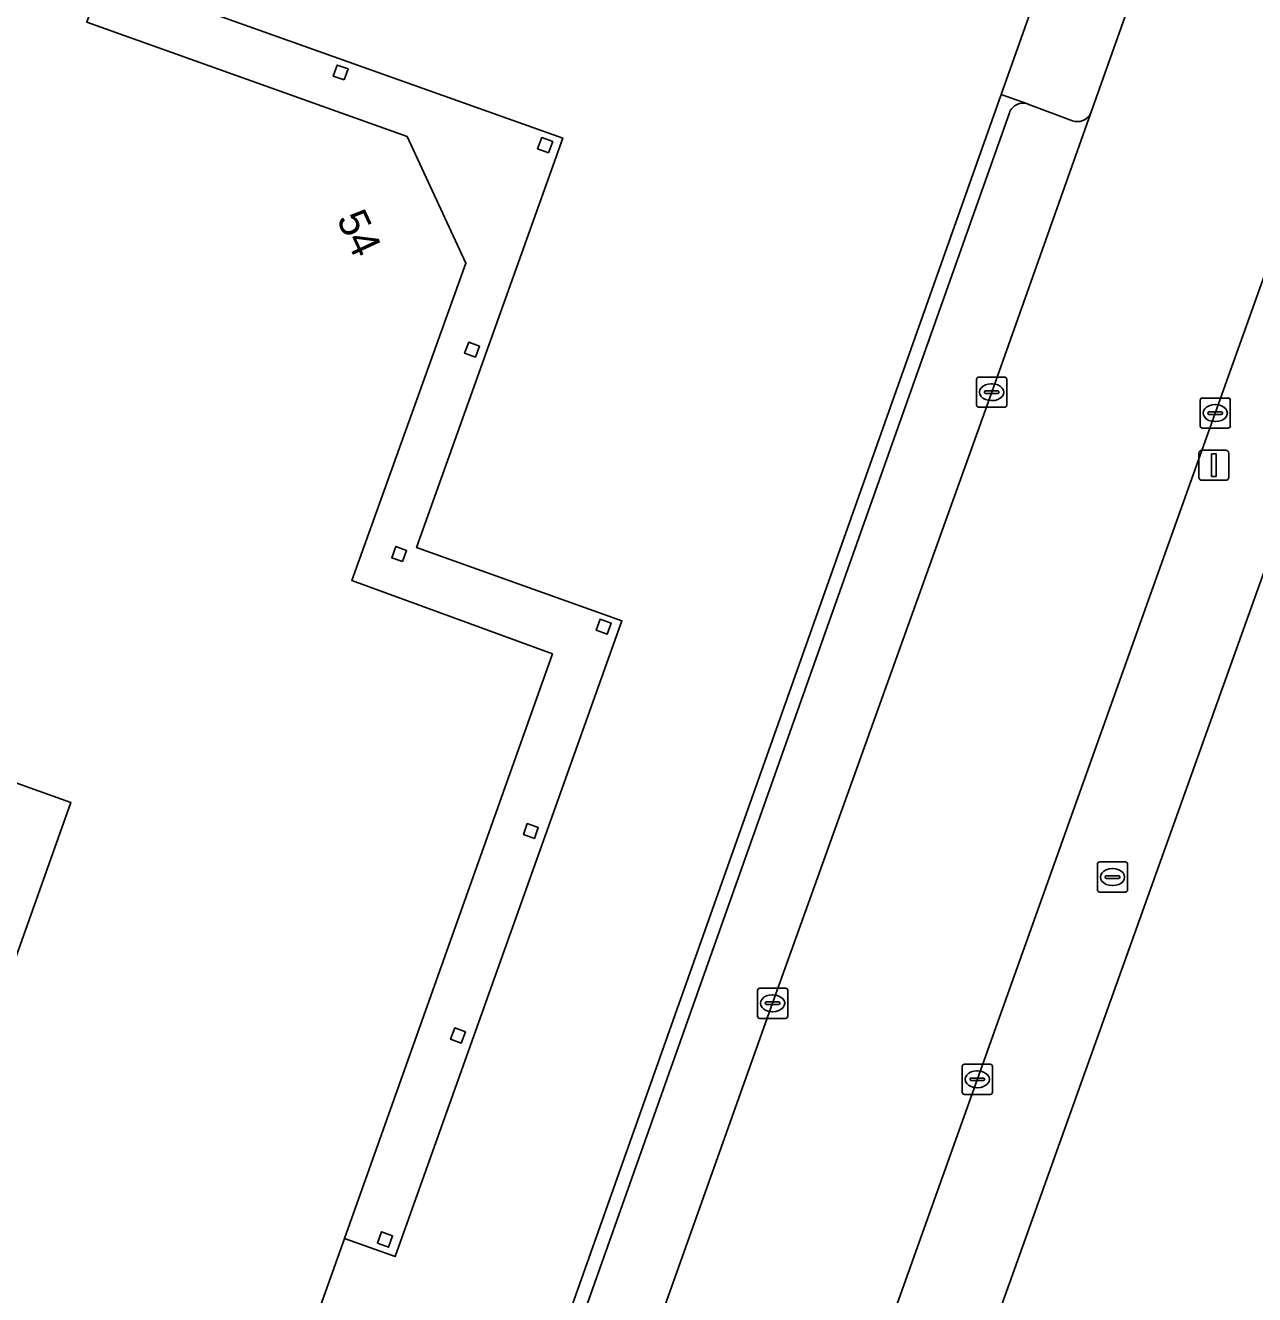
# Model space of a CAD drawing. Extents: x 155018 to 156648, y 383979 to 385733.
# Drawn here: x 155717.08 to 155757.84, y 385071.83 to 385113.92 of the extents above; entities that cross this region are included whole.
import ezdxf

# ---------------------------------------------------------------- set-up
doc = ezdxf.new("R2010")
doc.units = 0
for name, color, linetype in [('IMGEO_Brandkraan', 7, 'Continuous'), ('IMGEO_Erf', 7, 'Continuous'), ('IMGEO_Kolk', 7, 'Continuous'), ('IMGEO_Lichtmast', 7, 'Continuous'), ('IMGEO_Pand', 7, 'Continuous'), ('IMGEO_Pand_nummerreeks', 7, 'Continuous'), ('IMGEO_Pand_overbouw', 7, 'Continuous'), ('IMGEO_Parkeervlak_open', 7, 'Continuous'), ('IMGEO_Rijbaan_lokaal_gesloten', 7, 'Continuous'), ('IMGEO_Voetpad_open', 7, 'Continuous')]:
    doc.layers.add(name, color=color, linetype=linetype)

msp = doc.modelspace()

# ---------------------------------------------------------------- linework, layer by layer
at = {"layer": 'IMGEO_Brandkraan'}
for p, q in [((155752.632, 385085.25), (155752.632, 385086.102)), ((155752.707, 385086.176), (155753.559, 385086.176)), ((155753.12, 385085.956), (155753.145, 385085.956)), ((155753.633, 385086.102), (155753.633, 385085.25)), ((155752.891, 385085.67), (155752.891, 385085.682)), ((155753.329, 385085.633), (155752.931, 385085.633)), ((155752.934, 385085.719), (155753.332, 385085.719)), ((155753.375, 385085.682), (155753.375, 385085.67)), ((155753.559, 385085.176), (155752.707, 385085.176)), ((155753.143, 385085.396), (155753.118, 385085.396))]:
    msp.add_line(p, q, dxfattribs=at)
for points in [[(155752.632, 385085.25), (155752.632, 385086.102)], [(155752.707, 385086.176), (155753.559, 385086.176)], [(155753.633, 385086.102), (155753.633, 385085.25)], [(155753.559, 385085.176), (155752.707, 385085.176)]]:
    msp.add_lwpolyline(points, dxfattribs=at)
for centre, radius, start, end in [((155752.709, 385086.1), 0.0765, 91.552, 178.448), ((155752.709, 385086.1), 0.0765, 91.552, 178.448), ((155753.557, 385086.1), 0.0765, 1.552, 88.448), ((155753.557, 385086.1), 0.0765, 1.552, 88.448), ((155752.931, 385085.679), 0.0403, 85.8775, 175.7526), ((155752.928, 385085.669), 0.0366, 178.938, 274.7102), ((155753.332, 385085.676), 0.043, 264.8664, 352.4533), ((155753.336, 385085.681), 0.0386, 1.7309, 96.639), ((155752.709, 385085.252), 0.0765, 181.552, 268.448), ((155752.709, 385085.252), 0.0765, 181.552, 268.448), ((155753.557, 385085.252), 0.0765, 271.552, 358.448), ((155753.557, 385085.252), 0.0765, 271.552, 358.448)]:
    msp.add_arc(centre, radius, start, end, dxfattribs=at)
for centre, major_axis, ratio, start_param, end_param in [((155753.119, 385085.676), (-0.387, 0.002), 0.722429, 4.712389, 7.853982), ((155753.144, 385085.676), (-0.39, 0.002), 0.717154, 1.570796, 4.712389)]:
    msp.add_ellipse(centre, major_axis=major_axis, ratio=ratio, start_param=start_param, end_param=end_param, dxfattribs=at)
at = {"layer": 'IMGEO_Erf'}
for points in [[(155694.342, 384956.978), (155694.915, 384958.585), (155709.077, 384998.076), (155709.767, 385000), (155717.522, 385021.627), (155721.797, 385033.581), (155723.78, 385039.191), (155749.439, 385111.623), (155754.279, 385125.284), (155751.396, 385130.416), (155717.596, 385142.395), (155670.014, 385159.249), (155661.245, 385162.355), (155620.236, 385176.93), (155602.298, 385183.305), (155601.269, 385183.671), (155551.448, 385201.401), (155546.604, 385198.733), (155542.42, 385187.249), (155529.708, 385151.464), (155526.702, 385143.011), (155526.061, 385141.208), (155524.297, 385136.458), (155523.434, 385136.779)], [(155841.725, 385076.189), (155812.458, 385090.276), (155811.925, 385090.532), (155810.841, 385091.052), (155764.43, 385113.324), (155764.255, 385112.835), (155733.568, 385027.069), (155733.054, 385025.589), (155730.642, 385018.653)]]:
    msp.add_lwpolyline(points, dxfattribs=at)
for points in [[(155670.263, 385124.691), (155674.13, 385128.38), (155672.13, 385129.15), (155674.66, 385131.64), (155676.67, 385130.92), (155681.04, 385135.1), (155695.29, 385130.022), (155721.45, 385120.7), (155719.12, 385114.03), (155729.74, 385110.24), (155731.69, 385106.03), (155727.91, 385095.51), (155734.56, 385093.08), (155727.662, 385073.693), (155721.63, 385056.74), (155716.5, 385058.59), (155715.32, 385055.2), (155712.89, 385057.75), (155713.52, 385059.62), (155709.03, 385061.25), (155718.594, 385088.148), (155701.503, 385094.257), (155707.612, 385111.348)], [(155727.65, 385112.111), (155727.294, 385112.24), (155727.427, 385112.606), (155727.783, 385112.477)], [(155734.431, 385109.695), (155734.071, 385109.831), (155734.21, 385110.199), (155734.57, 385110.064)], [(155732.01, 385102.912), (155731.65, 385103.046), (155731.786, 385103.412), (155732.146, 385103.279)], [(155729.587, 385096.136), (155729.23, 385096.266), (155729.367, 385096.641), (155729.723, 385096.511)], [(155736.01, 385093.859), (155736.142, 385094.227), (155736.504, 385094.097), (155736.372, 385093.729)], [(155733.602, 385087.084), (155733.725, 385087.448), (155734.09, 385087.325), (155733.966, 385086.96)], [(155731.184, 385080.3), (155731.322, 385080.676), (155731.674, 385080.547), (155731.537, 385080.171)], [(155728.756, 385073.538), (155728.895, 385073.912), (155729.263, 385073.776), (155729.125, 385073.402)]]:
    msp.add_lwpolyline(points, close=True, dxfattribs=at)
at = {"layer": 'IMGEO_Kolk'}
for p, q in [((155748.624, 385101.33), (155748.624, 385102.182)), ((155748.699, 385102.256), (155749.551, 385102.256)), ((155749.112, 385102.036), (155749.137, 385102.036)), ((155749.625, 385102.182), (155749.625, 385101.33)), ((155748.883, 385101.75), (155748.883, 385101.762)), ((155749.321, 385101.713), (155748.923, 385101.713)), ((155748.926, 385101.799), (155749.324, 385101.799)), ((155749.135, 385101.476), (155749.11, 385101.476)), ((155749.367, 385101.762), (155749.367, 385101.75)), ((155756.038, 385100.637), (155756.038, 385101.489)), ((155756.113, 385101.563), (155756.965, 385101.563)), ((155757.039, 385101.489), (155757.039, 385100.637)), ((155749.551, 385101.256), (155748.699, 385101.256)), ((155756.297, 385101.057), (155756.297, 385101.069)), ((155756.735, 385101.02), (155756.337, 385101.02)), ((155756.34, 385101.106), (155756.738, 385101.106)), ((155756.526, 385101.343), (155756.551, 385101.343)), ((155756.781, 385101.069), (155756.781, 385101.057)), ((155756.549, 385100.783), (155756.524, 385100.783)), ((155756.965, 385100.563), (155756.113, 385100.563)), ((155741.361, 385081.064), (155741.361, 385081.916)), ((155741.436, 385081.99), (155742.288, 385081.99)), ((155741.849, 385081.77), (155741.874, 385081.77)), ((155742.362, 385081.916), (155742.362, 385081.064)), ((155741.62, 385081.484), (155741.62, 385081.496)), ((155742.058, 385081.447), (155741.66, 385081.447)), ((155741.663, 385081.533), (155742.061, 385081.533)), ((155742.104, 385081.496), (155742.104, 385081.484)), ((155742.288, 385080.99), (155741.436, 385080.99)), ((155741.872, 385081.21), (155741.847, 385081.21)), ((155748.149, 385078.543), (155748.149, 385079.395)), ((155748.224, 385079.469), (155749.076, 385079.469)), ((155748.637, 385079.249), (155748.662, 385079.249)), ((155749.15, 385079.395), (155749.15, 385078.543)), ((155748.408, 385078.963), (155748.408, 385078.975)), ((155748.846, 385078.926), (155748.448, 385078.926)), ((155748.451, 385079.012), (155748.849, 385079.012)), ((155748.892, 385078.975), (155748.892, 385078.963)), ((155749.076, 385078.469), (155748.224, 385078.469)), ((155748.66, 385078.689), (155748.635, 385078.689))]:
    msp.add_line(p, q, dxfattribs=at)
for points in [[(155748.624, 385101.33), (155748.624, 385102.182)], [(155748.699, 385102.256), (155749.551, 385102.256)], [(155749.625, 385102.182), (155749.625, 385101.33)], [(155756.038, 385100.637), (155756.038, 385101.489)], [(155756.113, 385101.563), (155756.965, 385101.563)], [(155757.039, 385101.489), (155757.039, 385100.637)], [(155749.551, 385101.256), (155748.699, 385101.256)], [(155756.965, 385100.563), (155756.113, 385100.563)], [(155741.361, 385081.064), (155741.361, 385081.916)], [(155741.436, 385081.99), (155742.288, 385081.99)], [(155742.362, 385081.916), (155742.362, 385081.064)], [(155742.288, 385080.99), (155741.436, 385080.99)], [(155748.149, 385078.543), (155748.149, 385079.395)], [(155748.224, 385079.469), (155749.076, 385079.469)], [(155749.15, 385079.395), (155749.15, 385078.543)], [(155749.076, 385078.469), (155748.224, 385078.469)]]:
    msp.add_lwpolyline(points, dxfattribs=at)
for centre, radius, start, end in [((155748.701, 385102.18), 0.0765, 91.552, 178.448), ((155748.701, 385102.18), 0.0765, 91.552, 178.448), ((155749.549, 385102.18), 0.0765, 1.552, 88.448), ((155749.549, 385102.18), 0.0765, 1.552, 88.448), ((155748.923, 385101.759), 0.0403, 85.8775, 175.7526), ((155748.92, 385101.749), 0.0366, 178.938, 274.7102), ((155749.324, 385101.756), 0.043, 264.8664, 352.4533), ((155749.328, 385101.761), 0.0386, 1.7309, 96.639), ((155756.115, 385101.487), 0.0765, 91.552, 178.448), ((155756.115, 385101.487), 0.0765, 91.552, 178.448), ((155756.963, 385101.487), 0.0765, 1.552, 88.448), ((155756.963, 385101.487), 0.0765, 1.552, 88.448), ((155748.701, 385101.332), 0.0765, 181.552, 268.448), ((155748.701, 385101.332), 0.0765, 181.552, 268.448), ((155749.549, 385101.332), 0.0765, 271.552, 358.448), ((155749.549, 385101.332), 0.0765, 271.552, 358.448), ((155756.337, 385101.066), 0.0403, 85.8775, 175.7526), ((155756.334, 385101.056), 0.0366, 178.938, 274.7102), ((155756.738, 385101.063), 0.043, 264.8664, 352.4533), ((155756.742, 385101.068), 0.0386, 1.7309, 96.639), ((155756.115, 385100.639), 0.0765, 181.552, 268.448), ((155756.115, 385100.639), 0.0765, 181.552, 268.448), ((155756.963, 385100.639), 0.0765, 271.552, 358.448), ((155756.963, 385100.639), 0.0765, 271.552, 358.448), ((155741.438, 385081.914), 0.0765, 91.552, 178.448), ((155741.438, 385081.914), 0.0765, 91.552, 178.448), ((155742.286, 385081.914), 0.0765, 1.552, 88.448), ((155742.286, 385081.914), 0.0765, 1.552, 88.448), ((155741.66, 385081.493), 0.0403, 85.8775, 175.7526), ((155741.657, 385081.483), 0.0366, 178.938, 274.7102), ((155742.061, 385081.49), 0.043, 264.8664, 352.4533), ((155742.065, 385081.495), 0.0386, 1.7309, 96.639), ((155741.438, 385081.066), 0.0765, 181.552, 268.448), ((155741.438, 385081.066), 0.0765, 181.552, 268.448), ((155742.286, 385081.066), 0.0765, 271.552, 358.448), ((155742.286, 385081.066), 0.0765, 271.552, 358.448), ((155748.226, 385079.393), 0.0765, 91.552, 178.448), ((155748.226, 385079.393), 0.0765, 91.552, 178.448), ((155749.074, 385079.393), 0.0765, 1.552, 88.448), ((155749.074, 385079.393), 0.0765, 1.552, 88.448), ((155748.448, 385078.972), 0.0403, 85.8775, 175.7526), ((155748.445, 385078.962), 0.0366, 178.938, 274.7102), ((155748.849, 385078.969), 0.043, 264.8664, 352.4533), ((155748.853, 385078.974), 0.0386, 1.7309, 96.639), ((155748.226, 385078.545), 0.0765, 181.552, 268.448), ((155748.226, 385078.545), 0.0765, 181.552, 268.448), ((155749.074, 385078.545), 0.0765, 271.552, 358.448), ((155749.074, 385078.545), 0.0765, 271.552, 358.448)]:
    msp.add_arc(centre, radius, start, end, dxfattribs=at)
for centre, major_axis, ratio, start_param, end_param in [((155749.111, 385101.756), (-0.387, 0.002), 0.722429, 4.712389, 7.853982), ((155749.136, 385101.756), (-0.39, 0.002), 0.717154, 1.570796, 4.712389), ((155756.525, 385101.063), (-0.387, 0.002), 0.722429, 4.712389, 7.853982), ((155756.55, 385101.063), (-0.39, 0.002), 0.717154, 1.570796, 4.712389), ((155741.848, 385081.49), (-0.387, 0.002), 0.722429, 4.712389, 7.853982), ((155741.873, 385081.49), (-0.39, 0.002), 0.717154, 1.570796, 4.712389), ((155748.636, 385078.969), (-0.387, 0.002), 0.722429, 4.712389, 7.853982), ((155748.661, 385078.969), (-0.39, 0.002), 0.717154, 1.570796, 4.712389)]:
    msp.add_ellipse(centre, major_axis=major_axis, ratio=ratio, start_param=start_param, end_param=end_param, dxfattribs=at)
at = {"layer": 'IMGEO_Lichtmast'}
for p, q in [((155756.099, 385099.834), (155756.889, 385099.834)), ((155756.889, 385099.834), (155756.099, 385099.834)), ((155755.999, 385098.934), (155755.999, 385099.734)), ((155755.999, 385099.734), (155755.999, 385098.934)), ((155756.989, 385099.734), (155756.989, 385098.934)), ((155756.989, 385098.934), (155756.989, 385099.734)), ((155756.889, 385098.834), (155756.099, 385098.834)), ((155756.099, 385098.834), (155756.889, 385098.834))]:
    msp.add_line(p, q, dxfattribs=at)
msp.add_lwpolyline([(155756.419, 385099.709), (155756.569, 385099.709), (155756.569, 385098.959), (155756.419, 385098.959), (155756.419, 385099.709)], dxfattribs=at)
for centre, start, end in [((155756.099, 385099.734), 90, 180), ((155756.099, 385099.734), 90, 180), ((155756.889, 385099.734), 0, 90), ((155756.889, 385099.734), 360, 90), ((155756.099, 385098.934), 180, 270), ((155756.099, 385098.934), 180, 270), ((155756.889, 385098.934), 270, 0), ((155756.889, 385098.934), 270, 0)]:
    msp.add_arc(centre, 0.1, start, end, dxfattribs=at)
at = {"layer": 'IMGEO_Pand'}
for points in [[(155695.29, 385130.022), (155681.04, 385135.1), (155676.67, 385130.92), (155674.66, 385131.64), (155672.13, 385129.15), (155674.13, 385128.38), (155670.263, 385124.691), (155707.612, 385111.348), (155701.503, 385094.257), (155718.594, 385088.148), (155709.03, 385061.25), (155713.52, 385059.62), (155712.89, 385057.75), (155715.32, 385055.2), (155716.5, 385058.59), (155721.63, 385056.74), (155727.662, 385073.693), (155734.56, 385093.08), (155727.91, 385095.51), (155731.69, 385106.03), (155729.74, 385110.24), (155719.12, 385114.03), (155721.45, 385120.7)], [(155727.65, 385112.111), (155727.783, 385112.477), (155727.427, 385112.606), (155727.294, 385112.24)], [(155734.431, 385109.695), (155734.57, 385110.064), (155734.21, 385110.199), (155734.071, 385109.831)], [(155732.01, 385102.912), (155732.146, 385103.279), (155731.786, 385103.412), (155731.65, 385103.046)], [(155729.587, 385096.136), (155729.723, 385096.511), (155729.367, 385096.641), (155729.23, 385096.266)], [(155736.372, 385093.729), (155736.504, 385094.097), (155736.142, 385094.227), (155736.01, 385093.859)], [(155733.966, 385086.96), (155734.09, 385087.325), (155733.725, 385087.448), (155733.602, 385087.084)], [(155731.537, 385080.171), (155731.674, 385080.547), (155731.322, 385080.676), (155731.184, 385080.3)], [(155729.125, 385073.402), (155729.263, 385073.776), (155728.895, 385073.912), (155728.756, 385073.538)]]:
    msp.add_lwpolyline(points, close=True, dxfattribs=at)
at = {"layer": 'IMGEO_Pand_overbouw'}
msp.add_lwpolyline([(155695.89, 385131.702), (155695.29, 385130.022), (155721.45, 385120.7), (155719.12, 385114.03), (155729.74, 385110.24), (155731.69, 385106.03), (155727.91, 385095.51), (155734.56, 385093.08), (155727.662, 385073.693), (155729.342, 385073.093), (155736.863, 385094.173), (155730.056, 385096.601), (155734.902, 385110.184), (155721.359, 385115.016), (155723.764, 385121.757)], close=True, dxfattribs=at)
at = {"layer": 'IMGEO_Parkeervlak_open'}
for points in [[(155751.804, 385110.752), (155750.359, 385111.297)], [(155749.712, 385111.016), (155724.175, 385038.957), (155722.456, 385033.926), (155724.606, 385033.163), (155727.42, 385041.095), (155734.635, 385061.204)], [(155734.635, 385061.204), (155741.863, 385081.49), (155749.126, 385101.756), (155752.407, 385110.986)]]:
    msp.add_lwpolyline(points, dxfattribs=at)
for centre, radius, start, end in [((155750.163, 385110.864), 0.476, 65.614, 161.3377), ((155751.961, 385111.24), 0.513, 252.133, 330.2854)]:
    msp.add_arc(centre, radius, start, end, dxfattribs=at)
at = {"layer": 'IMGEO_Rijbaan_lokaal_gesloten'}
for points in [[(155764.837, 385117.429), (155755.507, 385119.738), (155752.407, 385110.986), (155749.126, 385101.756), (155741.863, 385081.49), (155734.635, 385061.204), (155727.42, 385041.095), (155724.606, 385033.163), (155719.998, 385020.177), (155712.839, 385000), (155711.66, 384996.694), (155697.277, 384956.434), (155683.176, 384916.819), (155680.471, 384909.27), (155672.406, 384886.601)], [(155679.062, 384884.306), (155679.409, 384885.386), (155683.078, 384895.663), (155693.322, 384923.959), (155698.719, 384939.029), (155712.551, 384977.822), (155712.738, 384978.347), (155715.089, 384984.941), (155720.459, 385000), (155723.632, 385008.98), (155724.976, 385012.761), (155727.017, 385018.428), (155728.003, 385021.255), (155731.055, 385029.838), (155733.848, 385037.615), (155741.439, 385058.768), (155756.537, 385101.063), (155759.644, 385109.754)]]:
    msp.add_lwpolyline(points, dxfattribs=at)
at = {"layer": 'IMGEO_Voetpad_open'}
for points in [[(155755.697, 385127.53), (155751.396, 385130.416), (155754.279, 385125.284), (155749.439, 385111.623), (155750.315, 385111.323), (155750.359, 385111.297), (155751.804, 385110.752)], [(155752.407, 385110.986), (155755.507, 385119.738)], [(155759.644, 385109.754), (155756.537, 385101.063), (155741.439, 385058.768), (155733.848, 385037.615), (155731.055, 385029.838), (155728.003, 385021.255), (155727.017, 385018.428), (155728.134, 385018.023), (155726.108, 385012.352), (155724.976, 385012.761), (155723.632, 385008.98), (155720.459, 385000), (155715.089, 384984.941), (155718.276, 384983.804), (155724.057, 385000), (155730.413, 385017.993), (155730.642, 385018.653), (155733.054, 385025.589), (155733.568, 385027.069), (155764.255, 385112.835)], [(155750.359, 385111.297), (155750.315, 385111.323), (155749.439, 385111.623), (155723.78, 385039.191), (155721.797, 385033.581)], [(155722.426, 385033.838), (155722.456, 385033.926), (155724.175, 385038.957), (155749.712, 385111.016)]]:
    msp.add_lwpolyline(points, dxfattribs=at)
for centre, radius, start, end in [((155750.163, 385110.864), 0.476, 65.614, 161.3377), ((155751.961, 385111.24), 0.513, 252.133, 330.2854)]:
    msp.add_arc(centre, radius, start, end, dxfattribs=at)

# ---------------------------------------------------------------- texts
at = {"layer": 'IMGEO_Pand_nummerreeks'}
msp.add_text('54', height=1, rotation=294.8528, dxfattribs=at).set_placement((155727.391, 385107.506))

doc.saveas('drawing.dxf')
